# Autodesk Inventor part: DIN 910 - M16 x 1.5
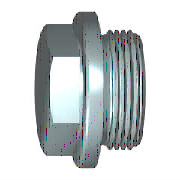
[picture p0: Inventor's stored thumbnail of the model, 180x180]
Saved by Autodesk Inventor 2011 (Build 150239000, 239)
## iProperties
IsCustomPart: 0
Created: 2010-02
Part Number: DIN 910 - M16 x 1.5
Material: Steel, Mild
Description: Screw Plug
Document SubType Name: Modeling
Standard: DIN 910
Designer: HTYCOON
Standards Organization: DIN
Language: en-US
Size Designation: M16 x 1.5
Categories: <MemberInstance><Categories><Category DisplayName="Other Parts" InternalName="5aa15e00-363f-49f2-933f-16f664388e3f" Mnemonic="OTHER"><Category DisplayName="Plug
Density: 1 g/cm^3
Author: HTYCOON
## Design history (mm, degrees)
revolve "Body" stored, may be unused: angle "d11" = 90 deg
sketch "Sketch2"
  geometry: L1 (9.815, 0)-(4.907, -8.5); L2 (4.907, -8.5)-(-4.907, -8.5); L3 (-4.907, -8.5)-(-9.815, 0); L4 (-9.815, 0)-(-4.907, 8.5); L5 (-4.907, 8.5)-(4.907, 8.5); L6 (4.907, 8.5)-(9.815, 0); 2 further points
  constraints: 12 end point, 1 coincident, 1 horizontal, 1 horizontal alignment, 12 other
extrude "Head" join sketch "Sketch2" distance "d12" = 6 (= KOH); taper "d13" = 0 deg
revolve "Chamfer1" stored, may be unused: angle "d16" = 90 deg
body "Solid1"
fillet "Fillet1" dims "d17" = 1 (= RR)
thread "Thread1" dims "d20" = 12 (= NLG), "d21" = 0
chamfer "Chamfer2" distance "d18" = 0.92018 (= GAL); stored, may be unused: second distance "d19" = 0.92017 (= -0.5 x GD1 + 0.5 x NND), angle "d24" = 45 deg
sketch "Sketch1"
  geometry: L1 (12, 0)-(12, 8); L2 (12, 8)-(2.25, 8); L3 (2.25, 8)-(1.44, 7.208); L4 (0.81, 7.208)-(0, 8); L5 (0, 8)-(0, 10.5); L6 (0, 10.5)-(-3, 10.5); L7 (-3, 10.5)-(-3, 9.815); L8 (-3, 9.815)-(-3.8, 9.815); L9 (-3.8, 9.815)-(-3.8, 0); L10 (-3.8, 0)-(12, 0); L11 (-6.96, 0)-(15.16, 0) reference; L12 (0, -2.1)-(0, 12.6) reference; L13 (2.373, 7.08)-(10.638, 7.08); A1 r 0.45 centre (1.125, 7.53) between (0.81, 7.208) and (1.44, 7.208)
  constraints: 22 end point, 6 parallel, 3 tangent, 2 collinear, 2 perpendicular, 2 point on circle, 1 centre point, 1 point on line, 1 vertical
  dimensions: "d0" = 0.45 radius of A1 (= 0.2 x GAL1); "d1" = 16 diameter of L2 L10 (= NND); "d2" = 21 diameter of L6 L10 (= KOD); "d3" = 12 distance between parallel lines of L1 L5 (= NLG); "d4" = 2.25 distance from line of L2.end L5 (= GAL1); "d5" = 1.125 horizontal distance of L2.end A1.centre (= 0.5 x GAL1); "d6" = 19.62991 diameter of L8 L10 (= n_D); "d7" = 3 distance of L5.end L6.end (= SD); "d8" = 0.8 distance of L7.end L8.end (= PHH); "d10" = 14.15965 diameter of L13 L10 (= GD1)
sketch "Sketch3"
  geometry: L1 (8.9, 9.815)-(9.8, 8.256); L2 (9.8, 8.256)-(9.8, 9.815); L3 (9.8, 9.815)-(8.9, 9.815); L4 (9.98, 0)-(8.72, 0) reference; 1 further point
  constraints: 6 end point, 1 coincident, 1 perpendicular, 1 vertical
  dimensions: "d14" = 0.9 distance of L2.end L1.start (= 0.15 x KOH); "d15" = 30 deg angle of L2 L1
other parameters: "NLG" = 12 [user parameter; used in 3 equation terms], "NND" = 16 [user parameter; used in 2 equation terms], "SD" = 3 [user parameter; used in 1 equation term], "PHH" = 0.8 [user parameter; used in 1 equation term], "SW" = 17 [user parameter; used in 1 equation term], "GAL1" = 2.25 [user parameter; used in 3 equation terms], "KOH" = 6 [user parameter; used in 2 equation terms], "KOD" = 21 [user parameter; used in 1 equation term], "GAL" = 0.92018 (= 0.61345 x PTC) [user parameter; used in 1 equation term], "RR" = 1 [user parameter; used in 1 equation term], "GD1" = 14.15965 (= THREADDIA - 1.2269 x PTC) [user parameter; used in 2 equation terms], "d22" = 0, "d23" = 0, "n_D" = 19.62991 (= 1.1547 x SW) [user parameter; used in 1 equation term], "GUL" = 0.92018 (= 0.61345 x PTC) [user parameter], "THREADDIA" = 16 [user parameter; used in 1 equation term], "GEL" = 12 (= NLG) [user parameter], "TOA" = 30 deg [user parameter], "TPU" = 6.66667 (computed from PTC) [user parameter], "PTC" = 1.5 [user parameter; used in 4 equation terms]
